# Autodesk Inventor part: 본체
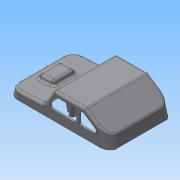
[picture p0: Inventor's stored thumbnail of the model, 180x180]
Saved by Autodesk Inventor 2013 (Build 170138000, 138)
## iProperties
Created: 2015-05
Part Number: 본체
Material: 일반
Document SubType Name: Modeling
Designer: Administrator
Density: 1 g/cm^3
Author: Administrator
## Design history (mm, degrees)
sketch "스케치1"
  geometry: L1 (61, -38)-(-61, -38); L2 (-61, -38)-(-61, 38); L3 (-61, 38)-(61, 38); L4 (61, 38)-(61, -38); L5 (61, -38)-(-61, 38); L6 (-61, -38)-(61, 38); 1 further point
  constraints: 12 end point, 2 midpoint, 2 parallel, 1 horizontal, 1 perpendicular
  dimensions: "d0" = 122 distance of L2.end L3.end; "d1" = 76 distance of L1.end L2.end
extrude "돌출1" new body sketch "스케치1" distance "d2" = 31; taper "d3" = 0 deg
node "작업 평면1"
node "작업 평면2"
sketch "스케치2"
  geometry: L1 (-1, 0)-(0, 0); L2 (0, 0)-(0, 76); L3 (0, 76)-(-1, 76); L4 (-1, 76)-(-1, 0); L5 (0, 0)-(0, 76) reference; 2 further points
  constraints: 8 end point, 2 parallel, 1 collinear, 1 horizontal, 1 horizontal alignment, 1 midpoint, 1 perpendicular
  dimensions: "d6" = 1 distance of L2.end L3.end; "d8" = 76 distance of L3.end L1.start
extrude "돌출2" cut sketch "스케치2" stored distance "d9" = 31; taper "d10" = 0 deg
sketch "스케치4"
  geometry: L1 (61, 31)-(61, 0) reference; L2 (61, 0)-(-60, 0) reference; L3 (-60, 0)-(-60, 1) reference; L4 (-60, 1)-(-61, 1) reference; L5 (-61, 1)-(-61, 31) reference; L6 (-61, 31)-(61, 31) reference; L7 (-61, 1)-(-57.738, 13.175); L8 (-31, 31)-(-61, 11); 1 further point
  constraints: 4 end point, 3 point on line
  dimensions: "d11" = 105 deg angle of L7 L2; "d12" = 30 horizontal distance of L8.start L4.end; "d13" = 20 vertical distance of L8.start L8.end
extrude "돌출3" cut sketch "스케치4" stored distance "d14" = 100; taper "d15" = 0 deg
sketch "스케치6"
  geometry: L1 (-57.738, 13.175)-(-31, 31) reference; L2 (-31, 31)-(61, 31) reference; L3 (61, 31)-(61, 1) reference; L4 (61, 1)-(60, 1) reference; L5 (60, 1)-(60, 0) reference; L6 (60, 0)-(-60, 0) reference; L7 (-60, 0)-(-60, 1) reference; L8 (-60, 1)-(-61, 1) reference; L9 (-61, 1)-(-57.738, 13.175) reference; L10 (61, 9)-(19, 11.201); L11 (19, 11.201)-(6.628, 31); L12 (61, 1)-(58.826, 9.114); 1 further point
  constraints: 6 end point, 3 point on line
  dimensions: "d16" = 9 distance from line of L10.start L6; "d17" = 3 deg angle of L6 L10; "d18" = 125 deg angle of L11 L10; "d19" = 42 horizontal distance of L10.end L10.start; "d24" = 105 deg angle of L12 L6
  node "절단 모서리 투영2"
extrude "돌출4" cut sketch "스케치6" stored distance "d20" = 100; taper "d21" = 0 deg
extrude "돌출5" cut sketch "스케치6" stored distance "d25" = 100; taper "d26" = 0 deg
sketch "스케치10"
  geometry: L1 (6.628, 31)-(19, 11.201) reference; L2 (19, 11.201)-(58.826, 9.114) reference; L3 (58.826, 9.114)-(61, 1) reference; L4 (61, 1)-(60, 1) reference; L5 (60, 1)-(60, 0) reference; L6 (60, 0)-(-60, 0) reference; L7 (-60, 0)-(-60, 1) reference; L8 (-60, 1)-(-61, 1) reference; L9 (-61, 1)-(-57.738, 13.175) reference; L10 (-57.738, 13.175)-(-31, 31) reference; L11 (-31, 31)-(6.628, 31) reference; L12 (5.52, 29)-(17.856, 9.258); L13 (17.856, 9.258)-(57.27, 7.193); L14 (57.27, 7.193)-(59.197, 0); L15 (-59.197, 0)-(-56.001, 11.929); L16 (-56.001, 11.929)-(-30.394, 29); L17 (-30.394, 29)-(5.52, 29); 1 further point
  constraints: 12 end point, 2 point on line, 2 other
  dimensions: "d27" = 2 distance between parallel lines of L11 L17; "d28" = 2 distance between parallel lines of L15 L9; "d29" = 2 distance between parallel lines of L1 L12; "d30" = 2 distance between parallel lines of L14 L3
extrude "돌출6" cut sketch "스케치10" stored distance "d31" = 72; taper "d32" = 0 deg
sketch "스케치11"
  geometry: L1 (117.738, 13.175)-(91, 31) reference; L2 (53.372, 31)-(91, 31) reference; L3 (53.372, 31)-(41, 11.201) reference; L4 (56.143, 26)-(46.77, 11); L5 (46.77, 11)-(80.77, 11); L6 (80.77, 11)-(80.77, 26); L7 (80.77, 26)-(56.143, 26); L8 (83.986, 26)-(83.986, 11); L9 (111.986, 11)-(89.486, 26); L10 (83.986, 11)-(111.986, 11); L11 (83.986, 26)-(89.486, 26); 1 further point
  constraints: 17 end point, 4 parallel, 4 perpendicular
  dimensions: "d33" = 5 distance between parallel lines of L4 L3; "d34" = 15 distance between parallel lines of L5 L7; "d35" = 5 distance between parallel lines of L7 L2; "d36" = 34 distance of L4.end L5.end; "d37" = 5 distance between parallel lines of L9 L1; "d39" = 5 distance between parallel lines of L11 L2; "d40" = 15 distance between parallel lines of L10 L11; "d41" = 28 distance of L8.end L9.start
extrude "돌출7" cut sketch "스케치11" stored distance "d42" = 72; taper "d43" = 0 deg
fillet "모깎기1" dims "d44" = 3
fillet "모깎기2" dims "d45" = 3.25
sketch "스케치12"
  geometry: L1 (-39.881, 76)-(0, 76) reference; L2 (-11.476, 51)-(-31.476, 51); L3 (-31.476, 51)-(-31.476, 25); L4 (-31.476, 25)-(-11.476, 25); L5 (-11.476, 25)-(-11.476, 51); L6 (-11.476, 51)-(-31.476, 25); L7 (-31.476, 51)-(-11.476, 25); L8 (-42.476, 76)-(-42.476, 0) reference; 2 further points
  constraints: 12 end point, 2 midpoint, 2 parallel, 1 horizontal, 1 perpendicular
  dimensions: "d49" = 20 distance of L4.end L3.end; "d50" = 26 distance of L3.end L2.end; "d51" = 38 distance from line of point (-21.476, 38) L1; "d52" = 11 distance between parallel lines of L3 L8
extrude "돌출8" join sketch "스케치12" distance "d53" = 5; taper "d54" = 0 deg
sketch "스케치14"
  geometry: L1 (6.628, 31)-(19, 11.201) reference; L2 (19, 11.201)-(30.461, 10.601) reference; L3 (30.461, 10.601)-(30.722, 15.594) reference; L4 (30.722, 15.594)-(50.695, 14.547) reference; L5 (50.695, 14.547)-(50.433, 9.554) reference; L6 (50.433, 9.554)-(58.826, 9.114) reference; L7 (58.826, 9.114)-(61, 1) reference; L8 (61, 1)-(60, 1) reference; L9 (60, 1)-(60, 0) reference; L10 (60, 0)-(59.197, 0) reference; L11 (59.197, 0)-(57.27, 7.193) reference; L12 (57.27, 7.193)-(17.856, 9.258) reference; L13 (17.856, 9.258)-(5.52, 29) reference; L14 (5.52, 29)-(-30.394, 29) reference; L15 (-30.394, 29)-(-56.001, 11.929) reference; L16 (-56.001, 11.929)-(-59.197, 0) reference; L17 (-59.197, 0)-(-60, 0) reference; L18 (-60, 0)-(-60, 1) reference; L19 (-60, 1)-(-61, 1) reference; L20 (-61, 1)-(-57.738, 13.175) reference; L21 (-57.738, 13.175)-(-31, 31) reference; L22 (-31, 31)-(6.628, 31) reference; L23 (30.461, 10.601)-(32.54, 15.498); L24 (50.433, 9.554)-(48.878, 14.642); 1 further point
  constraints: 4 end point, 2 point on line
  dimensions: "d57" = 70 deg angle of L23 L2; "d58" = 70 deg angle of L24 L6
extrude "돌출9" cut sketch "스케치14" stored distance "d59" = 5; taper "d60" = 0 deg
node "작업 평면4"
fillet "모깎기3" dims "d81" = 3
fillet "모깎기4" dims "d82" = 3
node "작업 평면5"
sketch "스케치18"
  geometry: C1 r 3 at (-40, 0); C2 r 3 at (40, 0); C3 r 3 at (0, -22); C4 r 3 at (0, 22); 1 further point
  constraints: 4 centre point, 2 horizontal alignment, 2 vertical alignment
  dimensions: "d84" = 6 diameter of C1; "d85" = 6 diameter of C2; "d86" = 6 diameter of C3; "d87" = 6 diameter of C4; "d88" = 40 distance of C1.centre point (0, 0); "d89" = 40 distance of C2.centre point (0, 0); "d90" = 22 distance of C3.centre point (0, 0); "d91" = 22 distance of C4.centre point (0, 0)
extrude "돌출11" join sketch "스케치18" stored distance "d92" = 5; taper "d93" = 2 deg
node "작업 평면6"
sketch "스케치20"
  geometry: L1 (38, 9.114)-(38, 1) reference; L2 (-38, 9.114)-(38, 9.114) reference; L3 (-38, 1)-(-38, 9.114) reference; A1 r 4 centre (-21, 1) between (-17, 1) and (-25, 1); A2 r 4 centre (-10, 1) between (-6, 1) and (-14, 1); A3 r 4 centre (10, 1) between (14, 1) and (6, 1); A4 r 4 centre (21, 1) between (25, 1) and (17, 1); 1 further point
  constraints: 8 point on circle, 4 centre point, 13 other
  dimensions: "d105" = 8 diameter of A1; "d106" = 8 diameter of A2; "d107" = 8 diameter of A3; "d108" = 8 diameter of A4; "d109" = 10 horizontal distance of A2.centre point (0, 0); "d110" = 11 distance of A1.centre A2.centre; "d111" = 10 horizontal distance of A3.centre point (0, 0); "d113" = 11 distance of A4.centre A3.centre
extrude "돌출12" join sketch "스케치20" stored distance "d114" = 5; taper "d115" = 0 deg
chamfer "모따기1" distance "d116" = 1; stored, may be unused: second distance "d117" = 2, angle "d118" = 45 deg
fillet "모깎기5" dims "d119" = 12
fillet "모깎기6" dims "d120" = 12
fillet "모깎기7" dims "d121" = 12
fillet "모깎기8" dims "d122" = 12
fillet "모깎기9" dims "d123" = 12
fillet "모깎기10" dims "d124" = 3
fillet "모깎기11" dims "d125" = 3
fillet "모깎기13" dims "d127" = 3
sketch "스케치21"
  geometry: L1 (-56.001, 11.929)-(-59.197, 0) reference; L2 (-59.197, 0)-(-60, 0) reference; L3 (-60, 0)-(-60, 1) reference; L4 (-60, 1)-(-61, 1) reference; L5 (-61, 1)-(-58.03, 12.082) reference; L6 (-56.797, 13.802)-(-31.756, 30.496) reference; L7 (-30.092, 31)-(4.965, 31) reference; L8 (7.51, 29.59)-(18.172, 12.526) reference; L9 (20.56, 11.119)-(28.363, 10.71) reference; L10 (31.281, 12.534)-(31.719, 13.565) reference; L11 (34.637, 15.388)-(46.78, 14.752) reference; L12 (49.492, 12.633)-(49.819, 11.563) reference; L13 (52.531, 9.444)-(56.649, 9.228) reference; L14 (59.39, 7.009)-(61, 1) reference; L15 (61, 1)-(60, 1) reference; L16 (60, 1)-(60, 0) reference; L17 (60, 0)-(59.197, 0) reference; L18 (59.197, 0)-(57.27, 7.193) reference; L19 (57.27, 7.193)-(43.242, 7.928) reference; L20 (43.242, 7.928)-(43, 1) reference; L21 (43, 1)-(37, 1) reference; L22 (37, 1)-(36.746, 8.268) reference; L23 (36.746, 8.268)-(17.856, 9.258) reference; L24 (17.856, 9.258)-(5.52, 29) reference; L25 (5.52, 29)-(-30.394, 29) reference; L26 (-30.394, 29)-(-36.156, 25.159) reference; L27 (-36.156, 25.159)-(-37, 1) reference; L28 (-37, 1)-(-43, 1) reference; L29 (-43, 1)-(-43.669, 20.15) reference; L30 (-43.669, 20.15)-(-56.001, 11.929) reference; L31 (-35, 3)-(-45, 3); L32 (-45, 3)-(-47.566, 17.552); L33 (-35, 3)-(-30.418, 28.984); L34 (-40, 3)-(-40, 21.058); L35 (-30.418, 28.984)-(-47.566, 17.552); A1 r 3 centre (-55.133, 11.306) between (-56.797, 13.802) and (-58.03, 12.082) reference; A2 r 3 centre (-30.092, 28) between (-30.092, 31) and (-31.756, 30.496) reference; A3 r 3 centre (4.965, 28) between (7.51, 29.59) and (4.965, 31) reference; A4 r 3 centre (20.717, 14.115) between (18.172, 12.526) and (20.56, 11.119) reference; A5 r 3 centre (28.52, 13.706) between (28.363, 10.71) and (31.281, 12.534) reference; A6 r 3 centre (34.48, 12.393) between (34.637, 15.388) and (31.719, 13.565) reference; A7 r 3 centre (46.623, 11.756) between (49.492, 12.633) and (46.78, 14.752) reference; A8 r 3 centre (52.688, 12.44) between (49.819, 11.563) and (52.531, 9.444) reference; A9 r 3 centre (56.492, 6.232) between (59.39, 7.009) and (56.649, 9.228) reference; 1 further point
  constraints: 10 end point, 2 point on line, 1 collinear, 1 midpoint, 1 parallel, 1 perpendicular
  dimensions: "d135" = 2 horizontal distance of L31.start L27.end; "d136" = 2 distance between parallel lines of L28 L31; "d137" = 10 distance of L31.start L31.end; "d138" = 20 deg angle of L32 L33; "d139" = 10 deg angle of L32 L34
extrude "돌출13" join sketch "스케치21" stored distance "d140" = 2; taper "d141" = 0 deg
node "작업 평면7"
sketch "스케치24"
  geometry: L1 (59.197, 0)-(56.001, 11.929) reference; L2 (56.001, 11.929)-(30.394, 29) reference; L3 (30.394, 29)-(3.978, 29) reference; L4 (3.978, 29)-(3, 1) reference; L5 (3, 1)-(-3, 1) reference; L6 (-3, 1)-(-3.978, 29) reference; L7 (-3.978, 29)-(-5.52, 29) reference; L8 (-5.52, 29)-(-17.856, 9.258) reference; L9 (-17.856, 9.258)-(-57.27, 7.193) reference; L10 (-57.27, 7.193)-(-59.197, 0) reference; L11 (-59.197, 0)-(-60, 0) reference; L12 (-60, 0)-(-60, 1) reference; L13 (-60, 1)-(-63, 1) reference; L14 (-63, 1)-(-63, 3.828) reference; L15 (-62, 4.873)-(-59.962, 4.873) reference; L16 (-59.962, 4.873)-(-59.39, 7.009) reference; L17 (-56.649, 9.228)-(-20.56, 11.119) reference; L18 (-18.172, 12.526)-(-7.51, 29.59) reference; L19 (-4.965, 31)-(30.092, 31) reference; L20 (31.756, 30.496)-(56.797, 13.802) reference; L21 (58.03, 12.082)-(61, 1) reference; L22 (61, 1)-(60, 1) reference; L23 (60, 1)-(60, 0) reference; L24 (60, 0)-(59.197, 0) reference; L25 (-5, 3)-(5, 3); L26 (5, 3)-(9.585, 29); L27 (-5, 3)-(-8.69, 23.927); L28 (0, 3)-(0, 22.149); L29 (-8.69, 23.927)-(-5.52, 29); L30 (9.585, 29)-(-5.52, 29); A1 r 3 centre (-56.492, 6.232) between (-56.649, 9.228) and (-59.39, 7.009) reference; A2 r 3 centre (-20.717, 14.115) between (-20.56, 11.119) and (-18.172, 12.526) reference; A3 r 3 centre (-4.965, 28) between (-4.965, 31) and (-7.51, 29.59) reference; A4 r 3 centre (30.092, 28) between (31.756, 30.496) and (30.092, 31) reference; A5 r 3 centre (55.133, 11.306) between (58.03, 12.082) and (56.797, 13.802) reference; 1 further point
  constraints: 12 end point, 2 collinear, 2 point on line, 1 midpoint, 1 parallel, 1 perpendicular, 1 vertical alignment, 1 other
  dimensions: "d156" = 10 distance of L25.start L25.end; "d158" = 2 distance between parallel lines of L5 L25; "d159" = 20 deg angle of L26 L27; "d160" = 10 deg angle of L27 L28
extrude "돌출15" join sketch "스케치24" stored distance "d161" = 2; taper "d162" = 0 deg
node "작업 평면8"
sketch "스케치26"
  geometry: L1 (59.197, 0)-(56.001, 11.929) reference; L2 (56.001, 11.929)-(30.394, 29) reference; L3 (30.394, 29)-(3.978, 29) reference; L4 (3.978, 29)-(3, 1) reference; L5 (3, 1)-(-3, 1) reference; L6 (-3, 1)-(-3.978, 29) reference; L7 (-3.978, 29)-(-5.52, 29) reference; L8 (-5.52, 29)-(-17.856, 9.258) reference; L9 (-17.856, 9.258)-(-57.27, 7.193) reference; L10 (-57.27, 7.193)-(-59.197, 0) reference; L11 (-59.197, 0)-(-60, 0) reference; L12 (-60, 0)-(-60, 1) reference; L13 (-60, 1)-(-63, 1) reference; L14 (-63, 1)-(-63, 3.828) reference; L15 (-62, 4.873)-(-59.962, 4.873) reference; L16 (-59.962, 4.873)-(-59.39, 7.009) reference; L17 (-56.649, 9.228)-(-20.56, 11.119) reference; L18 (-18.172, 12.526)-(-7.51, 29.59) reference; L19 (-4.965, 31)-(30.092, 31) reference; L20 (31.756, 30.496)-(56.797, 13.802) reference; L21 (58.03, 12.082)-(61, 1) reference; L22 (61, 1)-(60, 1) reference; L23 (60, 1)-(60, 0) reference; L24 (60, 0)-(59.197, 0) reference; L25 (-5, 3)-(5, 3); L26 (5, 3)-(9.585, 29); L27 (-5, 3)-(-8.69, 23.927); L28 (0, 3)-(0, 16.343); L29 (-8.69, 23.927)-(-5.52, 29); L30 (9.585, 29)-(-5.52, 29); A1 r 3 centre (-56.492, 6.232) between (-56.649, 9.228) and (-59.39, 7.009) reference; A2 r 3 centre (-20.717, 14.115) between (-20.56, 11.119) and (-18.172, 12.526) reference; A3 r 3 centre (-4.965, 28) between (-4.965, 31) and (-7.51, 29.59) reference; A4 r 3 centre (30.092, 28) between (31.756, 30.496) and (30.092, 31) reference; A5 r 3 centre (55.133, 11.306) between (58.03, 12.082) and (56.797, 13.802) reference; 1 further point
  constraints: 12 end point, 2 collinear, 2 point on line, 1 midpoint, 1 parallel, 1 perpendicular, 1 vertical alignment, 1 other
  dimensions: "d164" = 2 distance between parallel lines of L5 L25; "d165" = 10 distance of L25.start L25.end; "d166" = 20 deg angle of L26 L27; "d167" = 10 deg angle of L27 L28
extrude "돌출16" join sketch "스케치26" stored distance "d168" = 2; taper "d169" = 0 deg
sketch "스케치28"
  geometry: L1 (34.87, 35.042)-(46.285, 35.042) reference; C1 r 3 at (0, 0) reference; C2 r 3 at (0, 44) reference; C3 r 3 at (-40, 22) reference; C4 r 3 at (40, 22) reference; 5 further points
  constraints: 4 coincident
hole "구멍1" sketch "스케치28" at (-40, 22), (0, 0), (0, 44), (40, 22) diameter "d170" = 3.242; stored, may be unused: countersink angle "d174" = 90 deg, drill point angle "d176" = 118 deg; dims "d171" = 9, "d172" = 4, "d173" = 2, "d175" = 11
sketch "스케치29"
  geometry: L1 (45, 3)-(35, 3); L2 (35, 3)-(34.046, 8.41); L3 (45, 3)-(45.845, 7.792); L4 (-56.001, 11.929)-(-59.197, 0) reference; L5 (-59.197, 0)-(-60, 0) reference; L6 (-60, 0)-(-60, 1) reference; L7 (-60, 1)-(-61, 1) reference; L8 (-61, 1)-(-58.03, 12.082) reference; L9 (-56.797, 13.802)-(-31.756, 30.496) reference; L10 (-30.092, 31)-(4.965, 31) reference; L11 (7.51, 29.59)-(18.172, 12.526) reference; L12 (20.56, 11.119)-(28.363, 10.71) reference; L13 (31.281, 12.534)-(31.719, 13.565) reference; L14 (34.637, 15.388)-(46.78, 14.752) reference; L15 (49.492, 12.633)-(49.819, 11.563) reference; L16 (52.531, 9.444)-(56.649, 9.228) reference; L17 (59.39, 7.009)-(61, 1) reference; L18 (61, 1)-(60, 1) reference; L19 (60, 1)-(60, 0) reference; L20 (60, 0)-(59.197, 0) reference; L21 (59.197, 0)-(57.27, 7.193) reference; L22 (57.27, 7.193)-(43.242, 7.928) reference; L23 (43.242, 7.928)-(43, 1) reference; L24 (43, 1)-(41.621, 1) reference; L25 (41.621, 1)-(41.621, 12) reference; L26 (41.621, 12)-(40, 12.974) reference; L27 (40, 12.974)-(38.379, 12) reference; L28 (38.379, 12)-(38.379, 1) reference; L29 (38.379, 1)-(37, 1) reference; L30 (37, 1)-(36.746, 8.268) reference; L31 (36.746, 8.268)-(17.856, 9.258) reference; L32 (17.856, 9.258)-(5.52, 29) reference; L33 (5.52, 29)-(-30.394, 29) reference; L34 (-30.394, 29)-(-30.418, 28.984) reference; L35 (-30.418, 28.984)-(-35, 3) reference; L36 (-35, 3)-(-36.93, 3) reference; L37 (-36.93, 3)-(-37, 1) reference; L38 (-37, 1)-(-38.379, 1) reference; L39 (-38.379, 1)-(-38.379, 12) reference; L40 (-38.379, 12)-(-40, 12.974) reference; L41 (-40, 12.974)-(-41.621, 12) reference; L42 (-41.621, 12)-(-41.621, 1) reference; L43 (-41.621, 1)-(-43, 1) reference; L44 (-43, 1)-(-43.07, 3) reference; L45 (-43.07, 3)-(-45, 3) reference; L46 (-45, 3)-(-47.566, 17.552) reference; L47 (-47.566, 17.552)-(-56.001, 11.929) reference; L48 (40, 3)-(40, 11.563); L49 (45.845, 7.792)-(34.046, 8.41); A1 r 3 centre (-55.133, 11.306) between (-56.797, 13.802) and (-58.03, 12.082) reference; A2 r 3 centre (-30.092, 28) between (-30.092, 31) and (-31.756, 30.496) reference; A3 r 3 centre (4.965, 28) between (7.51, 29.59) and (4.965, 31) reference; A4 r 3 centre (20.717, 14.115) between (18.172, 12.526) and (20.56, 11.119) reference; A5 r 3 centre (28.52, 13.706) between (28.363, 10.71) and (31.281, 12.534) reference; A6 r 3 centre (34.48, 12.393) between (34.637, 15.388) and (31.719, 13.565) reference; A7 r 3 centre (46.623, 11.756) between (49.492, 12.633) and (46.78, 14.752) reference; A8 r 3 centre (52.688, 12.44) between (49.819, 11.563) and (52.531, 9.444) reference; A9 r 3 centre (56.492, 6.232) between (59.39, 7.009) and (56.649, 9.228) reference; 1 further point
  constraints: 10 end point, 2 point on line, 1 collinear, 1 horizontal, 1 midpoint, 1 perpendicular, 1 vertical alignment
  dimensions: "d177" = 2 distance between parallel lines of L29 L1; "d178" = 10 distance of L1.start L1.end; "d179" = 20 deg angle of L2 L3; "d180" = 10 deg angle of L3 L48
extrude "돌출17" join sketch "스케치29" stored distance "d181" = 2; taper "d182" = 0 deg
node "솔리드1"
mirror "대칭1"
mirror "대칭2"
node "투영된 루프1"
node "투영된 루프3"
node "투영된 루프4"
node "투영된 루프5"
node "절단 모서리 투영1"
node "절단 모서리 투영4"
node "절단 모서리 투영6"
node "절단 모서리 투영8"
node "절단 모서리 투영10"
node "절단 모서리 투영11"
node "절단 모서리 투영12"
other parameters: "d4" = -5 deg, "d5" = -1, "d80" = 5 deg, "d83" = 1, "d96" = 10 deg, "d104" = -63, "d155" = 22, "d163" = -22
